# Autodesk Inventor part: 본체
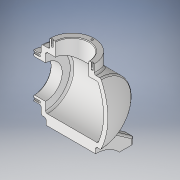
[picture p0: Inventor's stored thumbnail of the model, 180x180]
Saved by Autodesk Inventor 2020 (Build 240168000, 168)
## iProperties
Created: 2023-12
Part Number: 본체
Material: 일반
Document SubType Name: Modeling
Designer: 1강의실14
Density: 1 g/cm^3
Appearance: 기본값
Author: 1강의실14
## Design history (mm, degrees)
sketch "스케치1"
  geometry: L1 (-48, 77)-(60, 77); L2 (-48, 77)-(-48, 127); L3 (-48, 127)-(48.336, 127); L4 (-48, 77)-(60, 77); A1 r 113 centre (-53, 77) between (53.287, 38.632) and (48.336, 127); 1 further point
  constraints: 8 end point, 3 point on circle, 2 horizontal, 1 centre point, 1 horizontal alignment, 1 perpendicular, 1 vertical
  dimensions: "d1" = 108 distance of L1.start L1.end; "d3" = 100 diameter of L3 L1; "d7" = 77 vertical distance of point (0, 0) L1.start; "d8" = 48 horizontal distance of point (0, 0) L1.start; "d10" = 113 radius of A1
revolve "회전1" sketch "스케치1" stored, may be unused: angle "d11" = 90 deg
feature "쉘1" dims "d12" = 7
sketch "스케치2"
  geometry: C1 r 50 at (0, 0) reference; C2 r 36 at (0, 0); 1 further point
  constraints: 1 centre point, 1 coincident
  dimensions: "d13" = 72 diameter of C2
extrude "돌출1" join sketch "스케치2" distance "d14" = 12; taper "d15" = 0 deg
sketch "스케치3"
  geometry: C1 r 36 at (0, 0) reference; 2 further points
  constraints: 1 coincident
hole "구멍1" sketch "스케치3" at (0, 0) diameter "d16" = 54; stored, may be unused: countersink angle "d20" = 90 deg, drill point angle "d22" = 0 deg; dims "d17" = 5, "d18" = 4, "d19" = 2, "d21" = 19
sketch "스케치4" dims "d23" = 65
  geometry: L1 (0, 0)-(0, 32.5); C1 r 27 at (0, 0) reference; 1 further point
  constraints: 2 end point, 1 coincident, 1 vertical, 1 vertical alignment, 2 other
hole "구멍2" sketch "스케치4" at (0, 32.5) diameter "d24" = 3.242; stored, may be unused: countersink angle "d28" = 90 deg, drill point angle "d30" = 118 deg; dims "d25" = 8, "d26" = 4, "d27" = 2, "d29" = 10
sketch "스케치5"
  geometry: L1 (40, -62)-(-40, -62); L2 (-40, -62)-(-40, 62); L3 (-40, 62)-(40, 62); L4 (40, 62)-(40, -62); L5 (40, -62)-(-40, 62); L6 (-40, -62)-(40, 62); 1 further point
  constraints: 12 end point, 2 midpoint, 2 parallel, 1 horizontal, 1 perpendicular
  dimensions: "d34" = 80 distance of L2.end L3.end; "d35" = 124 distance of L1.end L2.end
extrude "돌출2" join sketch "스케치5" distance "d36" = 10; taper "d37" = 0 deg
sketch "스케치6"
  geometry: L1 (10, -62)-(10, 62) reference; L2 (10, 62)-(34.722, 26.694); L3 (10, -62)-(34.722, -26.694); L4 (0, 62)-(10, 62) reference; L5 (0, -62)-(10, -62) reference; A1 r 50 centre (77, 0) between (34.722, -26.694) and (34.722, 26.694) reference; 1 further point
  constraints: 4 end point, 2 point on circle
  dimensions: "d38" = 55 deg angle of L4 L2; "d39" = 55 deg angle of L5 L3
extrude "돌출3" join sketch "스케치6" stored distance "d40" = 80; taper "d41" = 0 deg
sketch "스케치7"
  geometry: L1 (124, 0)-(0, 0) reference; L2 (39.049, 17)-(84.951, 17); A1 r 52.096 centre (62, -35.096) between (100.5, 0) and (23.5, 0); 3 further points
  constraints: 2 end point, 2 horizontal alignment, 2 midpoint, 2 point on circle, 2 point on line, 2 vertical alignment, 1 centre point, 1 horizontal, 1 tangent
  dimensions: "d42" = 17 distance between parallel lines of L1 L2; "d43" = 77 distance of A1.start A1.end
extrude "돌출4" cut sketch "스케치7" extent not by distance; stored distance "d44" = 0; taper "d45" = 0 deg
node "작업 평면1"
node "작업 평면2"
sketch "스케치10"
  geometry: L1 (60, -36)-(60, 36) reference; C1 r 36 at (-2, 0); 1 further point
  constraints: 1 centre point, 1 coincident
  dimensions: "d60" = 72 diameter of C1; "d88" = 62 distance from line of L1 point (-2, 0)
extrude "돌출6" join sketch "스케치10" stored distance "d61" = 20; taper "d62" = 0 deg
sketch "스케치11"
  geometry: C1 r 36 at (0, 0) reference; C2 r 27 at (0, 0); 1 further point
  constraints: 1 centre point, 1 coincident
  dimensions: "d63" = 54 diameter of C2
extrude "돌출7" cut sketch "스케치11" stored distance "d64" = 20; taper "d65" = 0 deg
sketch "스케치12" dims "d66" = 65
  geometry: L1 (0, 0)-(0, 32.5); C1 r 27 at (0, 0) reference; 1 further point
  constraints: 2 end point, 1 coincident, 1 vertical, 1 vertical alignment, 2 other
hole "구멍4" sketch "스케치12" at (0, 32.5) diameter "d67" = 3.242; stored, may be unused: countersink angle "d71" = 90 deg, drill point angle "d73" = 118 deg; dims "d68" = 8, "d69" = 4, "d70" = 2, "d72" = 10
fillet "모깎기1" dims "d77" = 3
chamfer "모따기1" distance "d78" = 1; stored, may be unused: second distance "d79" = 2, angle "d80" = 45 deg
fillet "모깎기2" dims "d81" = 3
fillet "모깎기3" dims "d82" = 3
sketch "스케치8"
  geometry: L1 (20, 54)-(20, 62); L2 (27, 54)-(27, 62); L3 (13, 62)-(13, 54); L4 (40, 38.5)-(40, 62) reference; A1 r 7 centre (20, 54) between (13, 54) and (27, 54); A2 r 7 centre (20, 62) between (27, 62) and (13, 62); 2 further points
  constraints: 8 end point, 4 point on circle, 4 tangent, 2 centre point, 1 horizontal alignment, 1 midpoint, 1 parallel, 1 vertical
  dimensions: "d47" = 14 diameter of A2; "d48" = 20 distance from line of L4 L1.start; "d49" = 8 distance of L3.start L3.end
extrude "돌출5" cut sketch "스케치8" distance "d50" = 20; taper "d51" = 0 deg
sketch "스케치9"
  geometry: A1 r 7 centre (0, 0) between (-7, 0) and (7, 0) reference; A2 r 7 centre (40, 0) between (33, 0) and (47, 0) reference; A3 r 7 centre (0, -108) between (7, -108) and (-7, -108) reference; A4 r 7 centre (40, -108) between (47, -108) and (33, -108) reference; 5 further points
  constraints: 4 coincident
hole "구멍3" sketch "스케치9" at (0, 0), (40, 0), (0, -108), (40, -108) diameter "d52" = 9; stored, may be unused: countersink angle "d56" = 90 deg, drill point angle "d58" = 118 deg; dims "d53" = 8, "d54" = 4, "d55" = 2, "d57" = 10
node "작업 평면3"
sketch "스케치13"
  geometry: L1 (-60, 113)-(-60, 41) reference; L2 (-37, 0)-(37, 0) reference; 2 further points
  constraints: 1 other
  dimensions: "d84" = 62 distance from line of L1 point (2, 77); "d85" = 77 distance from line of L2 point (2, 77)
feature "엠보싱1" sketch "스케치13" dims "d1" = 108, "d3" = 100, "d7" = 77, "d8" = 48, "d10" = 113, "d17" = 5, "d86" = 0.5, "d87" = 0
feature "분할1"
node "솔리드1"
pattern_circular "원형 패턴1" dims angle "d32" = 360 deg
pattern_circular "원형 패턴2" dims angle "d75" = 360 deg
mirror "미러1"
mirror "미러2"
feature "A9D066F2-1C7D-4E18-AEED-F7BC21143FA4" dims "d16" = 54, "d17" = 5, "d18" = 4, "d19" = 2, "d20" = 90 deg, "d21" = 19, "d22" = 0
other parameters: "d46" = 6, "d59" = 142
